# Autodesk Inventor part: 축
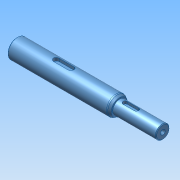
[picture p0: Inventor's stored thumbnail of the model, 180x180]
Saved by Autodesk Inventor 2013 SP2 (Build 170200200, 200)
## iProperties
Created: 2025-05
Part Number: 축
Material: Generic
Document SubType Name: Modeling
Designer: a
Density: 1 g/cm^3
Author: a
변환 표준: STEP AP214IS
전처리기: Build: 200, Release: 2013 SP2 Update 6 - Date: Thu 07/17/2014
전송 단위: 밀리미터
불확실성: 0.01
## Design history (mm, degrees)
node "축1"
node "솔리드1"
node "기준1"
